Omron CX-Programmer project NuevoProyecto (CX-Programmer 9.50)

# PLC NewPLC1: CQM1 CPU21

## Global symbols (name address type ; comment)
DM0 CHANNEL  ; 0
TIM001 BOOL  ; T1
TIM002 BOOL  ; T2
TIM003 BOOL  ; T3
TIM004 BOOL  ; T4
TIM005 BOOL  ; T5
TIM006 BOOL  ; T6
TIM007 BOOL  ; T7
TIM008 BOOL  ; T8

## Program P10_1 (no task)
Local symbols
EV1 100.04 BOOL  ; EV1=X6·Pm'
EV2 100.05 BOOL  ; EV2=X13·Pm'
EVA 100.00 BOOL  ; EVA=(X1+X10)·Pm'
EVB 100.01 BOOL  ; EVB=(X2+X9)Pm'
EVC 100.02 BOOL  ; EVC=X3·Pm'
EVD 100.03 BOOL  ; EVD=X8·Pm'
Etapa_0 10.00 BOOL
Etapa_1 10.01 BOOL
Etapa_10 10.10 BOOL
Etapa_11 10.11 BOOL
Etapa_12 10.12 BOOL
Etapa_13 10.13 BOOL
Etapa_14 10.14 BOOL
Etapa_2 10.02 BOOL
Etapa_3 10.03 BOOL
Etapa_4 10.04 BOOL
Etapa_5 10.05 BOOL
Etapa_6 10.06 BOOL
Etapa_7 10.07 BOOL
Etapa_8 10.08 BOOL
Etapa_9 10.09 BOOL
FC1 0.04 BOOL  ; Final carrera 1 (CNA)
FC2 0.05 BOOL  ; Final carrera 2 (CNA)
FC3 0.06 BOOL  ; Final carrera 3 (CNA)
FC4 0.07 BOOL  ; Final carrera 4 (CNA)
KCD 100.06 BOOL  ; KCD=(X1+X2+X3+X4)·Pm'
KCI 100.07 BOOL  ; KCI=(X8+X9+X10+X11)·Pm'
KV1D 101.00 BOOL  ; KV1D=X5·Pm'
KV1I 101.01 BOOL  ; KV1I=X7·Pm'
KV2D 101.02 BOOL  ; KV2D=X14·Pm'
KV2I 101.03 BOOL  ; KV2I=X12·Pm'
P 0.02 BOOL  ; Pulsador de paro (CNC)
Pm 15.00 BOOL  ; Pm=P·X0'+Pm·R'
R 0.03 BOOL  ; Pulsador de rearme (CNA)
m1 0.00 BOOL  ; Pulsador de marcha mezcla 1 (CNA)
m2 0.01 BOOL  ; Pulsador de marcha mezcla 2 (CNA)

### Section Sección1_Etapa_0
; Etapa 0

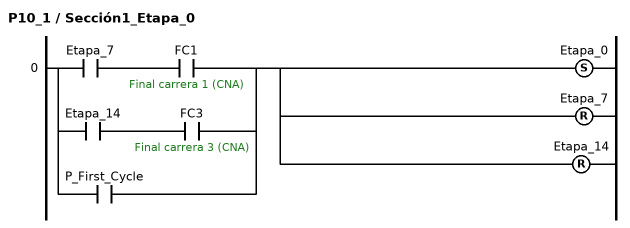
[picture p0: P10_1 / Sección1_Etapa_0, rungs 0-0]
; rung 0
LD Etapa_7
AND FC1  ; Final carrera 1 (CNA)
LD Etapa_14
AND FC3  ; Final carrera 3 (CNA)
ORLD
OR P_First_Cycle
SET Etapa_0
RSET Etapa_7
RSET Etapa_14

### Section Sección2_Mezcla_1_Etapas_1_a_7
; Etapas 1 ... 7

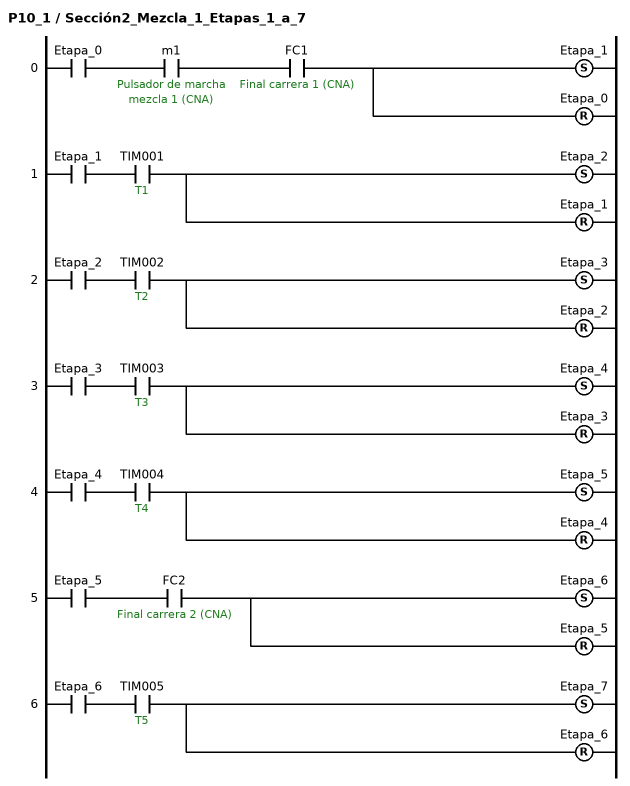
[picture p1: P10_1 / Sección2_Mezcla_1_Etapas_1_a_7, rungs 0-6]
; rung 0
LD Etapa_0
AND m1  ; Pulsador de marcha mezcla 1 (CNA)
AND FC1  ; Final carrera 1 (CNA)
SET Etapa_1
RSET Etapa_0
; rung 1
LD Etapa_1
AND TIM001  ; T1
SET Etapa_2
RSET Etapa_1
; rung 2
LD Etapa_2
AND TIM002  ; T2
SET Etapa_3
RSET Etapa_2
; rung 3
LD Etapa_3
AND TIM003  ; T3
SET Etapa_4
RSET Etapa_3
; rung 4
LD Etapa_4
AND TIM004  ; T4
SET Etapa_5
RSET Etapa_4
; rung 5
LD Etapa_5
AND FC2  ; Final carrera 2 (CNA)
SET Etapa_6
RSET Etapa_5
; rung 6
LD Etapa_6
AND TIM005  ; T5
SET Etapa_7
RSET Etapa_6

### Section Sección3_Mezcla_2_Etapas_8_a_14
; Etapas 8 ... 14

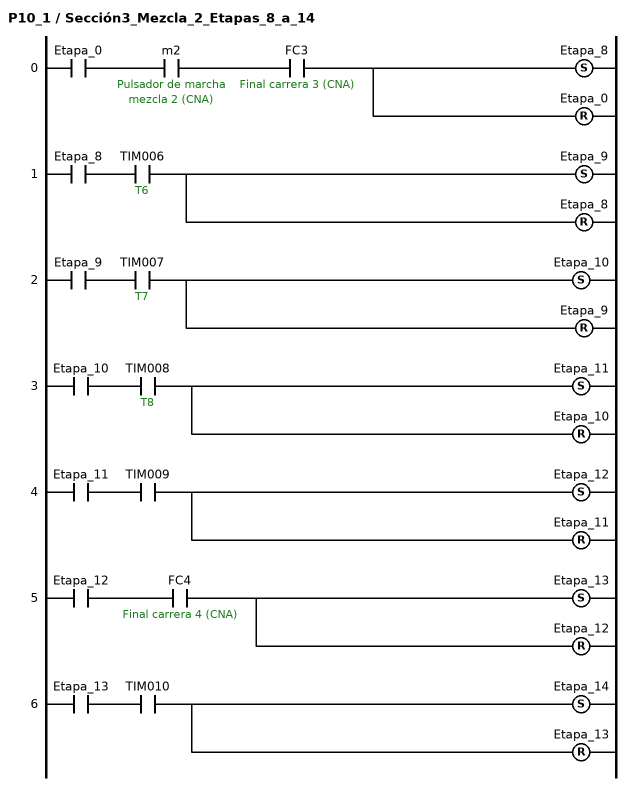
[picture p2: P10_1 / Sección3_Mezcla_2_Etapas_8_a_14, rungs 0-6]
; rung 0
LD Etapa_0
AND m2  ; Pulsador de marcha mezcla 2 (CNA)
AND FC3  ; Final carrera 3 (CNA)
SET Etapa_8
RSET Etapa_0
; rung 1
LD Etapa_8
AND TIM006  ; T6
SET Etapa_9
RSET Etapa_8
; rung 2
LD Etapa_9
AND TIM007  ; T7
SET Etapa_10
RSET Etapa_9
; rung 3
LD Etapa_10
AND TIM008  ; T8
SET Etapa_11
RSET Etapa_10
; rung 4
LD Etapa_11
AND TIM009
SET Etapa_12
RSET Etapa_11
; rung 5
LD Etapa_12
AND FC4  ; Final carrera 4 (CNA)
SET Etapa_13
RSET Etapa_12
; rung 6
LD Etapa_13
AND TIM010
SET Etapa_14
RSET Etapa_13

### Section Sección4_Temporizadores
; Temporizadores

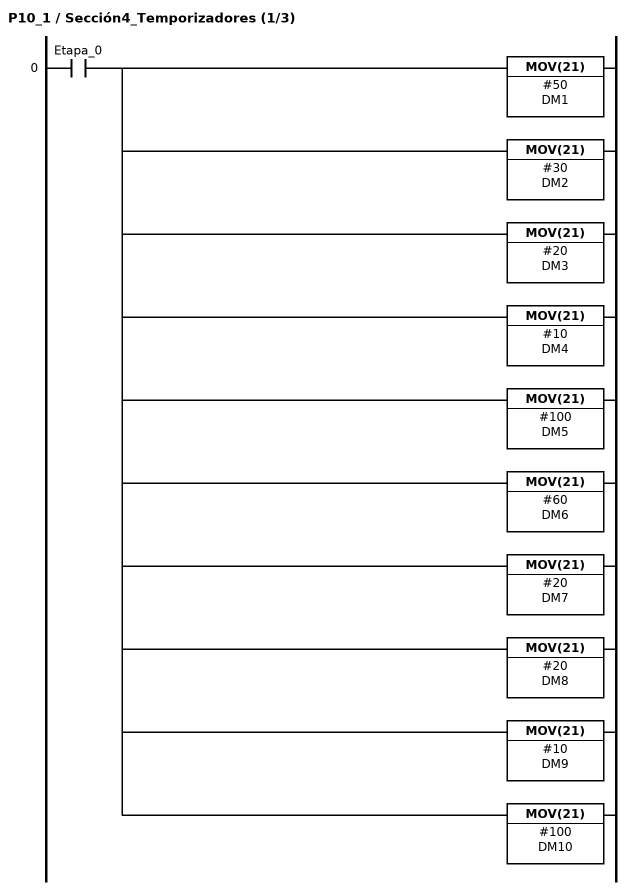
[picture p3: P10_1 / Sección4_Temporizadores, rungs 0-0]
; rung 0
LD Etapa_0
MOV(21) #50 DM1
MOV(21) #30 DM2
MOV(21) #20 DM3
MOV(21) #10 DM4
MOV(21) #100 DM5
MOV(21) #60 DM6
MOV(21) #20 DM7
MOV(21) #20 DM8
MOV(21) #10 DM9
MOV(21) #100 DM10

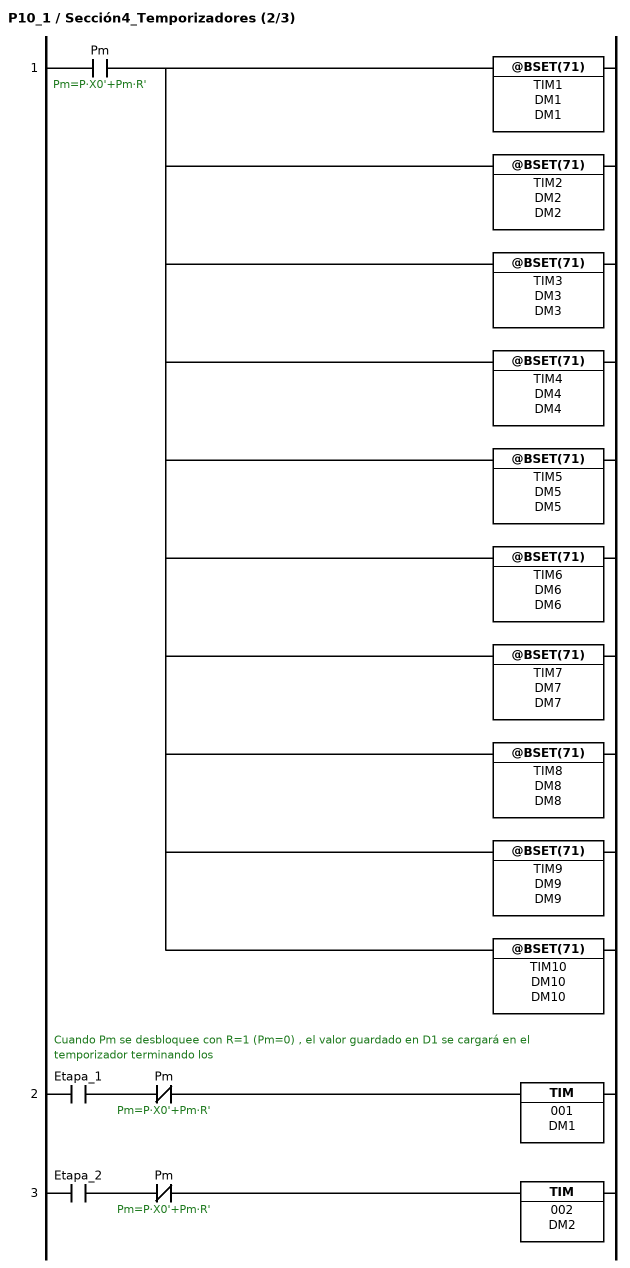
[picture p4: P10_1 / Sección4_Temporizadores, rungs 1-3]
; rung 1
LD Pm  ; Pm=P·X0'+Pm·R'
@BSET(71) TIM1 DM1 DM1  // La instrucción @BSET pasa a D1 el valor que le queda a T1 en el momento de pulsar P (Pm=P·X0'+Pm·R'=1)
@BSET(71) TIM2 DM2 DM2
@BSET(71) TIM3 DM3 DM3
@BSET(71) TIM4 DM4 DM4
@BSET(71) TIM5 DM5 DM5
@BSET(71) TIM6 DM6 DM6
@BSET(71) TIM7 DM7 DM7
@BSET(71) TIM8 DM8 DM8
@BSET(71) TIM9 DM9 DM9
@BSET(71) TIM10 DM10 DM10
; rung 2: Cuando Pm se desbloquee con R=1 (Pm=0) , el valor guardado en D1 se cargará en el temporizador terminando los
LD Etapa_1
ANDNOT Pm  ; Pm=P·X0'+Pm·R'
TIM 001 DM1  // segundos que le quedasen
; rung 3
LD Etapa_2
ANDNOT Pm  ; Pm=P·X0'+Pm·R'
TIM 002 DM2

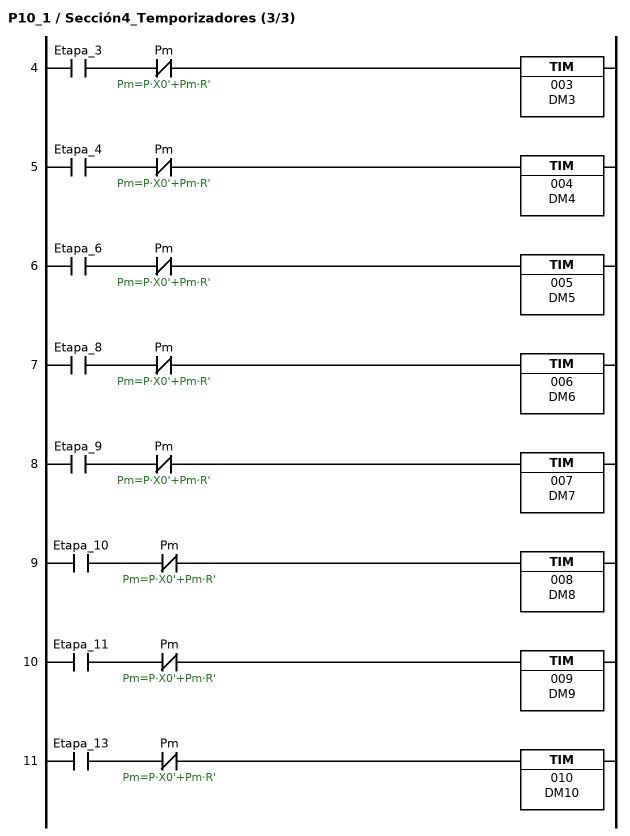
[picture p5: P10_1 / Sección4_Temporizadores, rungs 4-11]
; rung 4
LD Etapa_3
ANDNOT Pm  ; Pm=P·X0'+Pm·R'
TIM 003 DM3
; rung 5
LD Etapa_4
ANDNOT Pm  ; Pm=P·X0'+Pm·R'
TIM 004 DM4
; rung 6
LD Etapa_6
ANDNOT Pm  ; Pm=P·X0'+Pm·R'
TIM 005 DM5
; rung 7
LD Etapa_8
ANDNOT Pm  ; Pm=P·X0'+Pm·R'
TIM 006 DM6
; rung 8
LD Etapa_9
ANDNOT Pm  ; Pm=P·X0'+Pm·R'
TIM 007 DM7
; rung 9
LD Etapa_10
ANDNOT Pm  ; Pm=P·X0'+Pm·R'
TIM 008 DM8
; rung 10
LD Etapa_11
ANDNOT Pm  ; Pm=P·X0'+Pm·R'
TIM 009 DM9
; rung 11
LD Etapa_13
ANDNOT Pm  ; Pm=P·X0'+Pm·R'
TIM 010 DM10

### Section Sección5_Ecuación_Pm

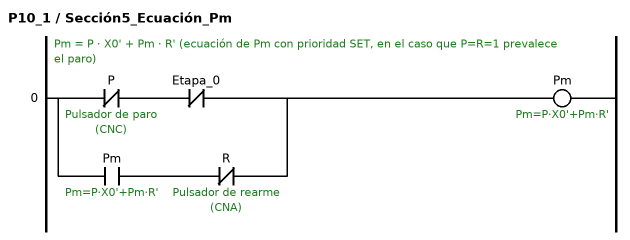
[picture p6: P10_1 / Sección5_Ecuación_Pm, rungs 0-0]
; rung 0: Pm = P · X0' + Pm · R' (ecuación de Pm con prioridad SET, en el caso que P=R=1 prevalece el paro)
LDNOT P  ; Pulsador de paro (CNC)
ANDNOT Etapa_0
LD Pm  ; Pm=P·X0'+Pm·R'
ANDNOT R  ; Pulsador de rearme (CNA)
ORLD
OUT Pm  ; Pm=P·X0'+Pm·R'

### Section Sección6_Salidas
; Salidas

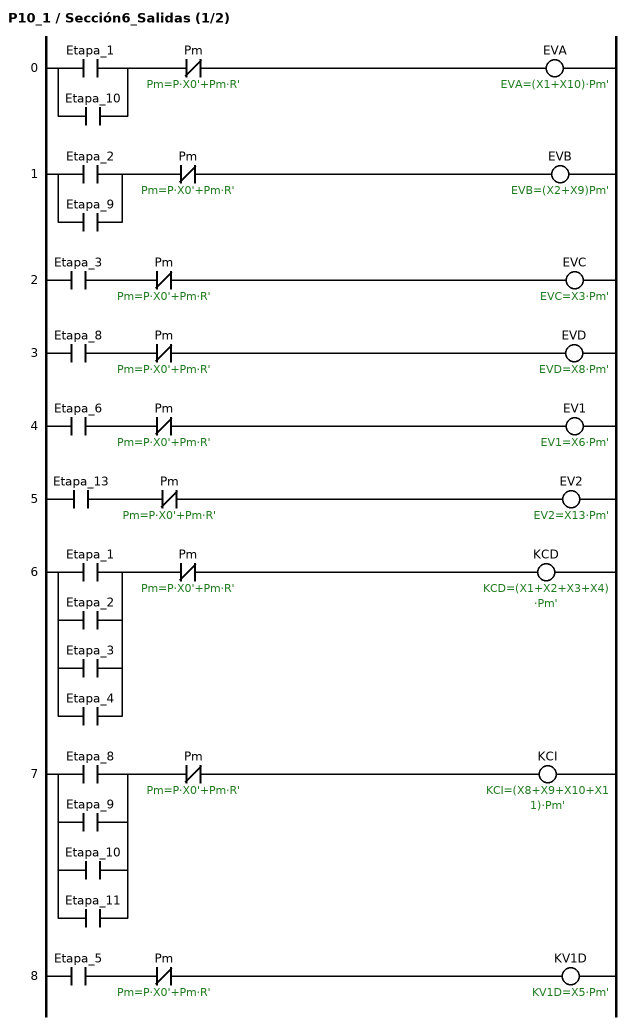
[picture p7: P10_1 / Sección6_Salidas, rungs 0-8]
; rung 0
LD Etapa_1
OR Etapa_10
ANDNOT Pm  ; Pm=P·X0'+Pm·R'
OUT EVA  ; EVA=(X1+X10)·Pm'
; rung 1
LD Etapa_2
OR Etapa_9
ANDNOT Pm  ; Pm=P·X0'+Pm·R'
OUT EVB  ; EVB=(X2+X9)Pm'
; rung 2
LD Etapa_3
ANDNOT Pm  ; Pm=P·X0'+Pm·R'
OUT EVC  ; EVC=X3·Pm'
; rung 3
LD Etapa_8
ANDNOT Pm  ; Pm=P·X0'+Pm·R'
OUT EVD  ; EVD=X8·Pm'
; rung 4
LD Etapa_6
ANDNOT Pm  ; Pm=P·X0'+Pm·R'
OUT EV1  ; EV1=X6·Pm'
; rung 5
LD Etapa_13
ANDNOT Pm  ; Pm=P·X0'+Pm·R'
OUT EV2  ; EV2=X13·Pm'
; rung 6
LD Etapa_1
OR Etapa_2
OR Etapa_3
OR Etapa_4
ANDNOT Pm  ; Pm=P·X0'+Pm·R'
OUT KCD  ; KCD=(X1+X2+X3+X4)·Pm'
; rung 7
LD Etapa_8
OR Etapa_9
OR Etapa_10
OR Etapa_11
ANDNOT Pm  ; Pm=P·X0'+Pm·R'
OUT KCI  ; KCI=(X8+X9+X10+X11)·Pm'
; rung 8
LD Etapa_5
ANDNOT Pm  ; Pm=P·X0'+Pm·R'
OUT KV1D  ; KV1D=X5·Pm'

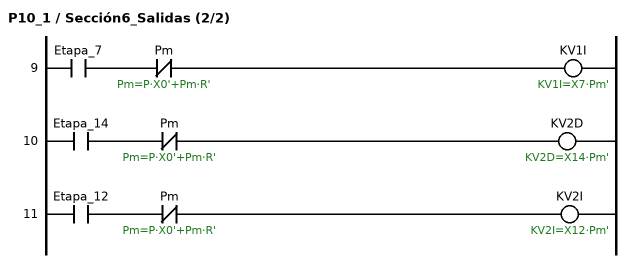
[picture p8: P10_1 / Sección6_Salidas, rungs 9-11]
; rung 9
LD Etapa_7
ANDNOT Pm  ; Pm=P·X0'+Pm·R'
OUT KV1I  ; KV1I=X7·Pm'
; rung 10
LD Etapa_14
ANDNOT Pm  ; Pm=P·X0'+Pm·R'
OUT KV2D  ; KV2D=X14·Pm'
; rung 11
LD Etapa_12
ANDNOT Pm  ; Pm=P·X0'+Pm·R'
OUT KV2I  ; KV2I=X12·Pm'

### Section Sección7_END
; END
; rung 0
END(01)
